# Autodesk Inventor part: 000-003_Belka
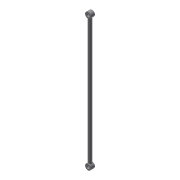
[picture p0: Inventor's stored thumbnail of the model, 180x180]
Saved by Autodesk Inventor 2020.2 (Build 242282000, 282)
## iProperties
Created: 2015-05
Part Number: 000-003_Belka
Material: Ogólny
Document SubType Name: Modeling
Designer: F.Stasiak
Density: 1 g/cm^3
Appearance: Domyślna
Manager: www.cadconsulting.pl
Company: Fabian Stasiak CAD Consulting
Author: F.Stasiak
Subject: Zbiór ćwiczeń. Autodesk Inventor 2020. Kurs podstawowy
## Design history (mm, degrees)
sketch "Szkic1"
  geometry: C1 r 10 at (0, 0); 1 further point
  constraints: 1 centre point, 1 coincident
  dimensions: "d0" = 20 diameter of C1
extrude "Wyciągnięcie proste1" new body sketch "Szkic1" stored distance "d1" = 800; taper "d2" = 0 deg
sketch "Szkic2"
  geometry: L1 (-10, -400)-(10, -400) reference; C1 r 17.5 at (0, -400); 1 further point
  constraints: 1 centre point, 1 midpoint
  dimensions: "d3" = 35 diameter of C1
extrude "Wyciągnięcie proste2" join sketch "Szkic2" stored distance "d4" = 25; taper "d5" = 0 deg
sketch "Szkic3"
  geometry: C1 r 17.5 at (0, 0) reference; C2 r 10 at (0, 0); 1 further point
  constraints: 1 centre point, 1 coincident
  dimensions: "d6" = 20 diameter of C2
extrude "Wyciągnięcie proste3" cut sketch "Szkic3" extent not by distance; stored distance "d7" = 25; taper "d8" = 0 deg
mirror "Odbicie lustrzane1"
node "Bryła1"
